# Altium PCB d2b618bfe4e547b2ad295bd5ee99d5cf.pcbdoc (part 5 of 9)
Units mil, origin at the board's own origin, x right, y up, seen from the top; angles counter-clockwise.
Board outline 5129 x 4161 mil, 8 copper layers (Top Layer, GND1, 内层2, VCC, 内层4, Inner5, GND2, Bottom Layer); 491 components, 452 nets, 2562 pads, 1124 vias.
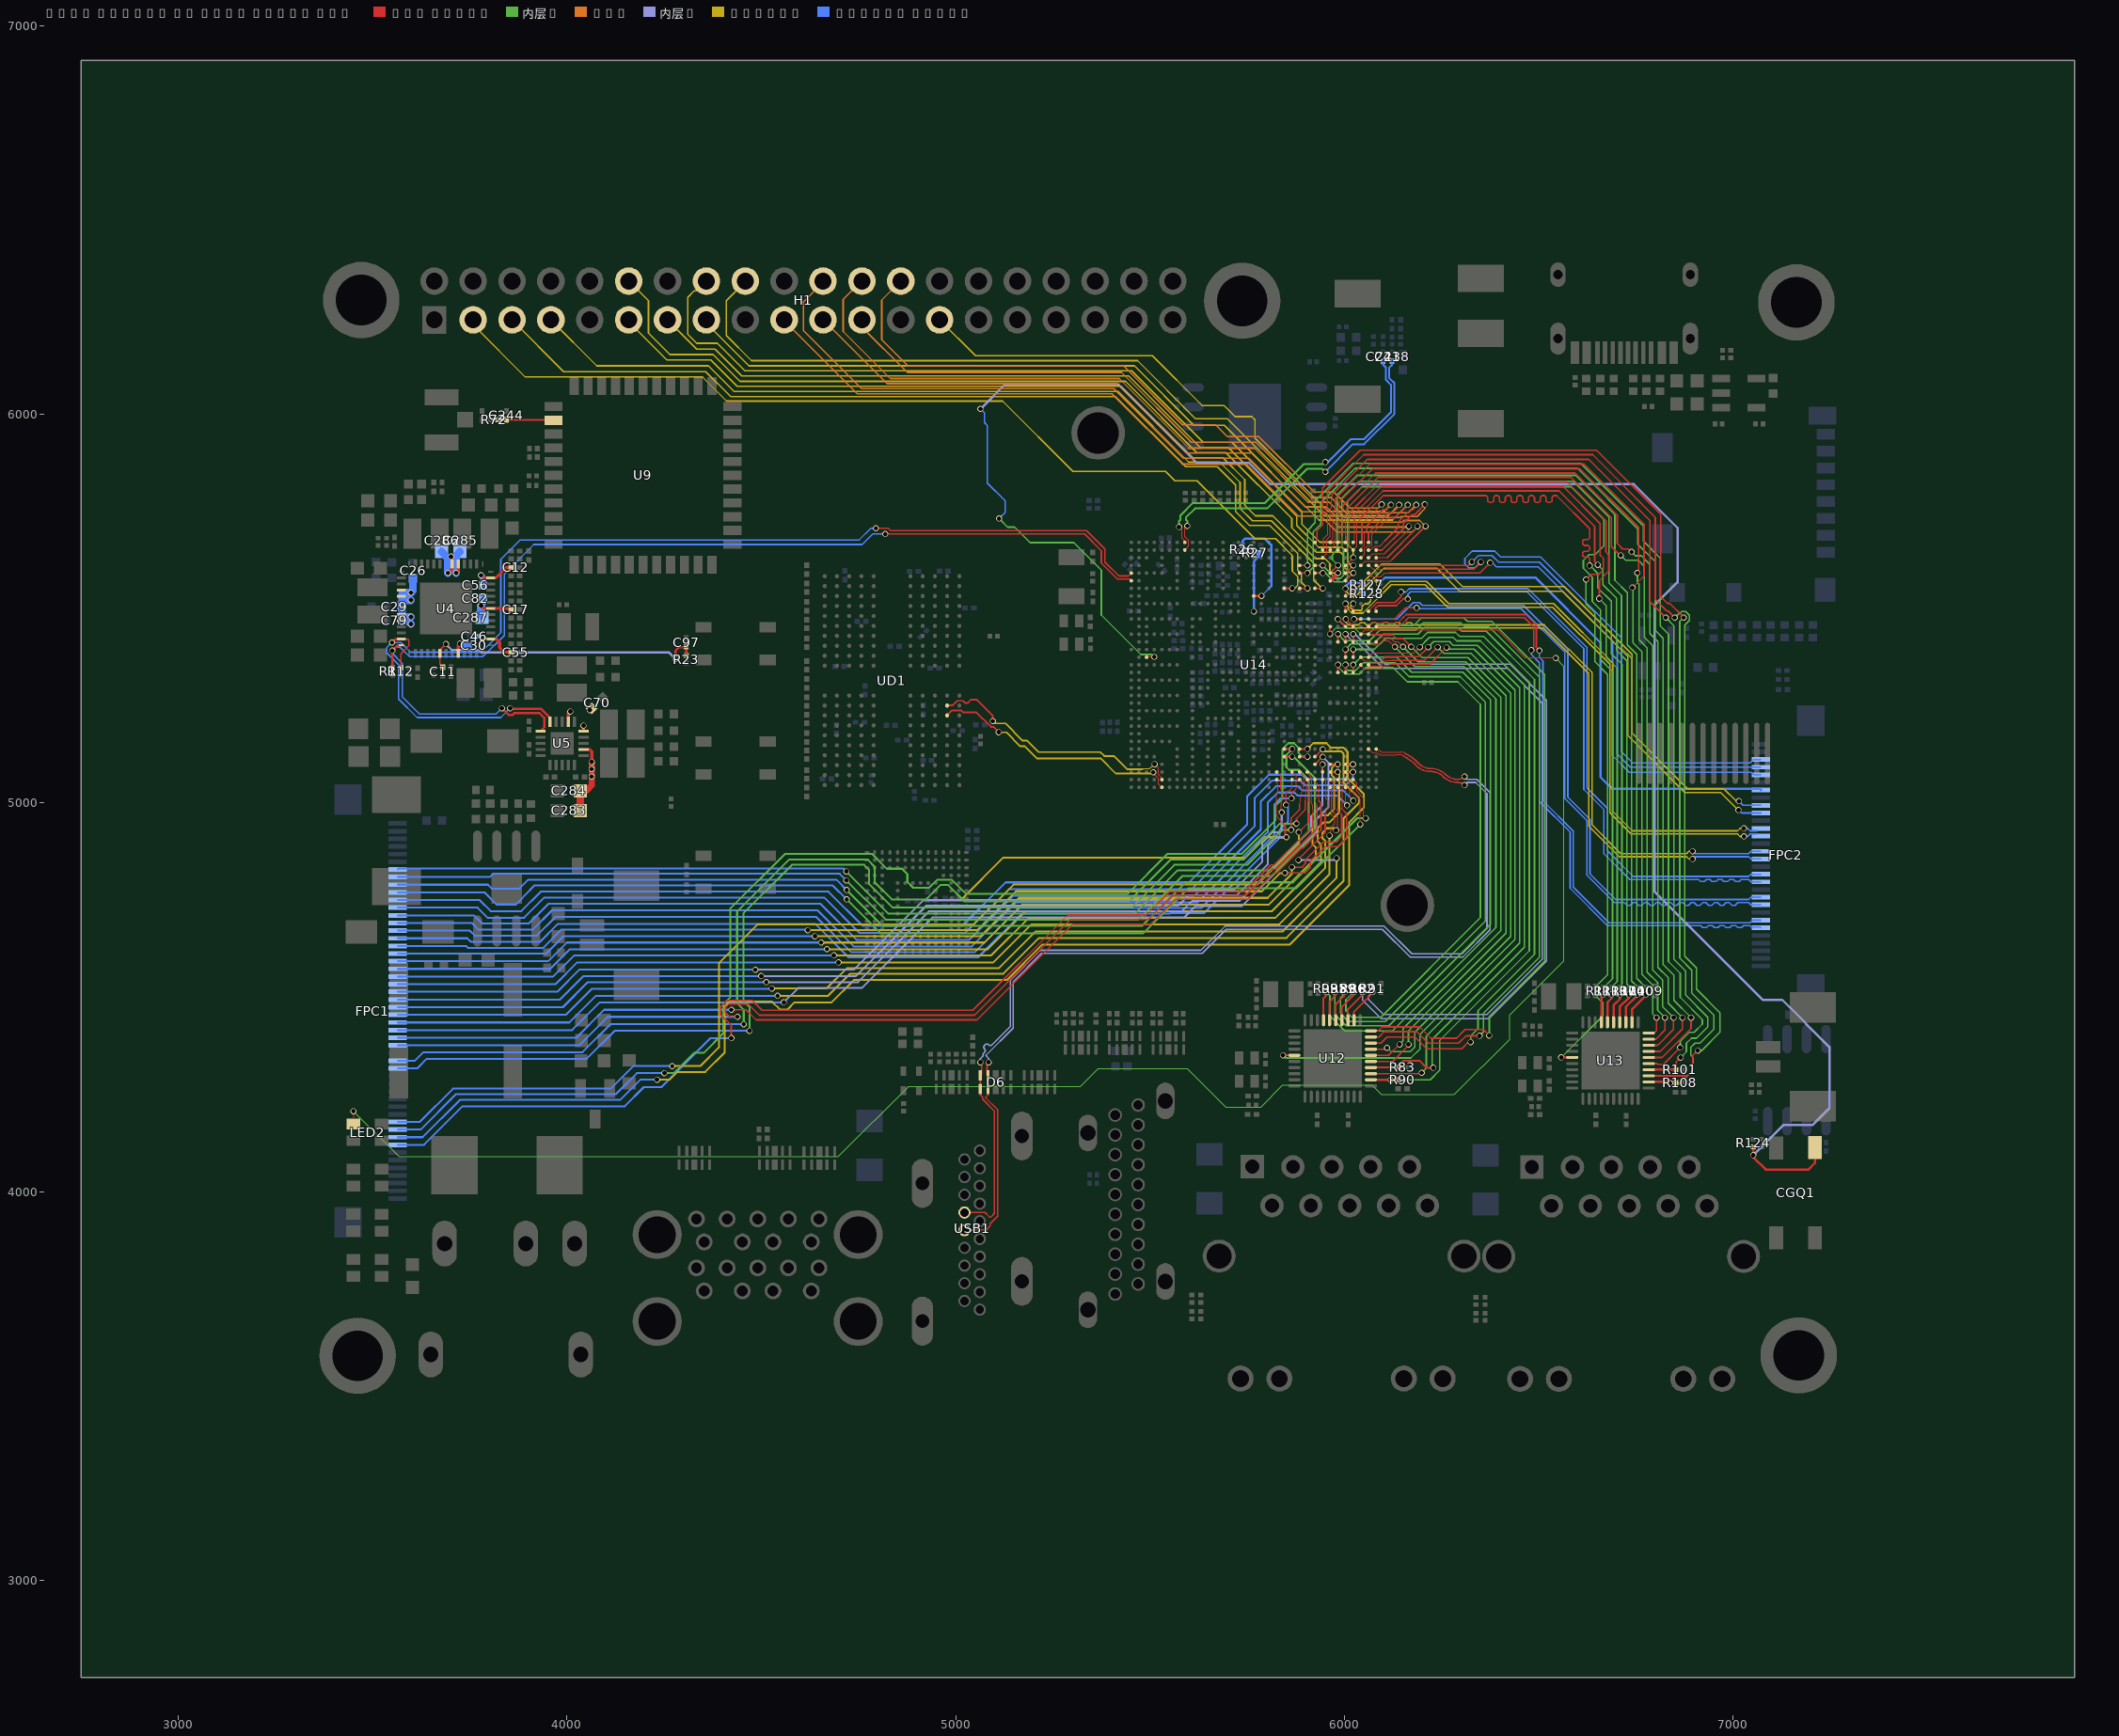
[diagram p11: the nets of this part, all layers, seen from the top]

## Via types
v1: diameter 15.75, hole 11.8, Top Layer to Bottom Layer, 497 vias
v2: diameter 15.7, hole 11.8, Top Layer to Bottom Layer, 335 vias
v3: diameter 15.75, hole 11.81, Top Layer to Bottom Layer, 279 vias
v4: diameter 24, hole 12, Top Layer to Bottom Layer, 13 vias

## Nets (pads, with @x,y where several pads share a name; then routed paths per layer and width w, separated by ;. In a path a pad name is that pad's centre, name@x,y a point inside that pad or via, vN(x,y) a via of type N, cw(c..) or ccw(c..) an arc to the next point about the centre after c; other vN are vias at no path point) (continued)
HTXCN: D6.5 D6.6 U14.B28 USB1.12 | length 2784.9
  Top Layer w3: U14.B28@6062.19,5138.91 6067.59,5133.51 ccw(c6078.21,5144.12) 6078.21,5129.11 6087.21,5129.11 6092.3,5124.02 6133.3,5124.02 cw(c6133.3,3512.36) 6141,5124 6145.7,5124.01 cw(c6145.7,5115.9) 6152,5121
  Top Layer w4: USB1.12@5022.89,3946.5 5075.5,3946.5 5087,3935 5091,3935 5100,3944 5100,4207.59 5069.46,4238.14 5069.46,4243.46 5063.63,4249.28 D6.6@5063.63,4264.67 D6.5@5063.63,4299.32 5067,4302.69 5067,4330 v1(5064,4333) ; 6152,5121 cw(c6096.03,5010.28) 6186.19,5095.5 ccw(c6219.89,5127.36) 6221,5081 cw(c6222.13,5033.84) 6255.36,5067.32 ccw(c6290.13,5102.35) 6290.13,5053 6292.13,5053 cw(c6292.13,5029.16) v1(6309,5046)
  内层4 w4: v1(5064,4333) 5064,4342.87 5070.49,4349.37 5070.49,4354.69 5074.36,4358.56 ccw(c5069.91,4363.01) 5074.36,4367.46 cw(c5078.81,4371.91) 5074.36,4376.36 5076.07,4378.07 cw(c5080.52,4373.61) 5084.97,4378.07 ccw(c5089.42,4382.52) 5093.87,4378.07 5141,4425.19 5141,4544.34 5217.68,4621.02 5631.02,4621.02 5693.02,4683.02 6102.98,4683.02 6174,4612 6302,4612 6367,4677 6367,5024 6338,5053 6316,5053 v1(6309,5046)
HTXCP: D6.4 D6.7 U14.A28 USB1.10 | length 2786.1
  Top Layer w3: U14.A28@6081.94,5138.93 6083.5,5137.3 ccw(c6086.37,5140.16) 6086.37,5136.11 6090.11,5136.11 6095.2,5131.02 6145.7,5131.01 cw(c6145.7,5112.46) 6155.61,5128.14
  Top Layer w4: USB1.10@5022.89,3900.97 5023.91,3902 5079,3902 5089,3912 5089,3918 5108.02,3937.02 5108.02,4210.91 5077.47,4241.46 5077.47,4243.46 5083.3,4249.28 D6.7@5083.3,4264.67 D6.4@5083.3,4299.33 5081,4301.63 5081,4329 v1(5085,4333) ; 6155.61,5128.14 cw(c6096.03,5010.28) 6192,5101 ccw(c6219.89,5127.36) 6220.81,5089 cw(c6222.13,5033.84) 6261,5073 ccw(c6290.13,5102.35) 6290.13,5061 6292.13,5061 ccw(c6292.13,5084.84) v1(6309,5068)
  内层4 w4: v1(5085,4333) 5085,4342.87 5078.51,4349.37 5078.51,4351.37 5148,4420.86 5148,4540 5221,4613 5634.34,4613 5696.34,4675 6098,4675 6169.02,4603.98 6305.32,4603.98 6375.02,4673.68 6375.02,5027.32 6341.34,5061 6316,5061 v1(6309,5068)
IR-RX: CGQ1.3 R124.1 U14.AL16 | length 5146.7
  Top Layer w3: U14.AL16@5491.39,5375.16 5510.16,5375.16 v2(5511,5376)
  Top Layer w6: R124.1@7052.62,4115.95 7052.62,4094.62 v2(7052,4094) 7052,4089 7084,4057 7194,4057 7210.88,4073.88 CGQ1.3@7210.88,4113.94
  内层2 w4: v2(5112,5732) 5134,5710 5152,5710 5192,5670 5304,5670 5375,5599 5375,5483.58 5476.58,5382 5505,5382 v2(5511,5376)
  内层4 w6: v2(5064,6014) 5127,6077 5419,6077 5621,5875 5755,5875 5810,5820 6745,5820 6857,5708 6857,5568 6798,5509 6798,4772 7076,4494 7126,4494 7248,4372 7248,4215 7205,4172 7130,4172 v2(7052,4094)
  Bottom Layer w4: v2(5064,6014) 5074,6004 5074,5979 5082,5971 5082,5823 5128,5777 5128,5748 v2(5112,5732)
LCD0-CLK: FPC1.43 U14.K31 | length 2944.3
  Top Layer w3: U14.K31@5904.64,5079.71 5914.45,5065.42 5915.07,5056.38 5914.99,5041.24 5914.45,5032.98 5915.07,5021.24 5914.22,5003.55 5917.93,4993.2 5918.93,4973.19
  Top Layer w4: v1(4423,4395) 4423,4428 4396,4455 4396,4476 4412,4492 4477,4492 4502,4467 5044,4467 5289,4712 5490,4712 5550,4772 5742,4772 5811,4841 5819,4841 5882,4904 5885,4904 5919,4938 5919,4973
  Bottom Layer w5: FPC1.43@3564.97,4120.52 3632.51,4120.52 3732,4220 4149,4220 4198,4269 4243,4269 4369,4395 v1(4423,4395)
LCD0-D0: FPC1.7 U14.N28 | length 2757.5
  Top Layer w5: U14.N28@5845.72,5138.93 v1(5865.72,5138.93)
  内层2 w5: v1(4719,4824) 4828,4715 5460,4715 5572,4827 5808,4827 5909,4928 5909,5060 5884,5085 5858,5085 5851,5092 5851,5124.22 v1(5865.72,5138.93)
  Bottom Layer w5: FPC1.7@3564.97,4829.18 3566.97,4831.18 4711.82,4831.18 v1(4719,4824)
LCD0-D1: FPC1.8 U14.N29 | length 2746.6
  Top Layer w5: U14.N29@5845.72,5119.25 v1(5865.72,5119.25)
  内层2 w5: v1(4719,4801) 4820,4700 5471,4700 5583,4812 5813,4812 5924,4923 5924,5065 5869.75,5119.25 v1(5865.72,5119.25)
  Bottom Layer w5: FPC1.8@3564.97,4809.48 3801.68,4809.48 3810.2,4818 4702,4818 v1(4719,4801)
LCD0-D2: FPC1.9 U14.D32 | length 2780.5
  Top Layer w3: U14.D32@6022.88,5060.51 6032.77,5050.61 6032.77,5030.23 6050,5013 6050,4966 v1(6055,4961)
  内层2 w5: v1(4720,4776) 4812,4684 5480,4684 5592,4796 5868,4796 6033,4961 v1(6055,4961)
  Bottom Layer w5: FPC1.9@3564.97,4789.81 3797.2,4789.81 3807,4780 3878,4780 3901,4803 4693,4803 v1(4720,4776)
LCD0-D3: FPC1.10 U14.D33 | length 2780
  Top Layer w3: U14.D33@6022.85,5040.79 6022.85,5026.85 6041,5008.7 v1(6041,4945)
  内层2 w5: v1(4720,4752) 4807,4665 5483,4665 5599,4781 5877,4781 v1(6041,4945)
  Bottom Layer w5: FPC1.10@3564.97,4770.11 3787.89,4770.11 3819,4739 3869,4739 3905,4775 3905,4776 3917,4788 4684,4788 v1(4720,4752)
LCD0-D4: FPC1.11 U14.E30 | length 2782.8
  Top Layer w5: U14.E30@6003.2,5099.56 v1(6022.2,5099.56)
  Bottom Layer w5: FPC1.11@3564.97,4750.44 3775.57,4750.44 3804,4722 3883,4722 3933,4772 4673,4772 4761,4684 5017,4684 5129,4796 5601,4796 5750,4945 5750,5017 5806,5073 5891,5073 5903,5061 5998.32,5061 6008,5070.68 6008,5093.57 6013.99,5099.56 v1(6022.2,5099.56)
LCD0-D5: FPC1.12 U14.E31 | length 2778.9
  Top Layer w5: U14.E31@6003.2,5079.88 v1(6022.2,5079.88)
  Bottom Layer w5: FPC1.12@3564.97,4730.74 3770.26,4730.74 3796,4705 3890,4705 3942,4757 4662,4757 4753,4666 5025,4666 5137,4778 5607,4778 5769,4940 5769,5012 5815,5058 5886,5058 5898,5046 6004,5046 6022.2,5064.2 v1(6022.2,5079.88)
LCD0-D6: FPC1.13 U14.E32 | length 2810.2
  Top Layer w3: U14.E32@6003.23,5060.51 6012.98,5050.75 6012.98,5016.02 v1(6023,5006)
  Bottom Layer w5: FPC1.13@3564.97,4711.06 3760.93,4711.06 3782,4690 3902,4690 3953,4741 4652,4741 4745,4648 5035,4648 5148,4761 5614,4761 5785,4932 5785,5004 5824,5043 5881,5043 5892,5032 5997,5032 v1(6023,5006)
LCD0-D7: FPC1.14 U14.E33 | length 2779.1
  Top Layer w3: U14.E33@6003.18,5040.81 6003.18,4997.82 v1(6007,4994)
  Bottom Layer w5: FPC1.14@3564.97,4691.38 3755.62,4691.38 3773,4674 3912,4674 3962,4724 4645,4724 4738,4631 5042,4631 5156,4745 5623,4745 5803,4925 5803,5001 5829,5027 5872,5027 5880,5019 5982,5019 v1(6007,4994)
LCD0-D8: FPC1.15 U14.M31 | length 2648.4
  Top Layer w3: U14.M31@5865.45,5080.07 5875.25,5070.27 5875.25,5035.39 5870.86,5031
  Top Layer w4: v1(5864,5012) 5864,5024.14 5870.86,5031
  Bottom Layer w5: FPC1.15@3564.97,4671.69 3750.3,4671.69 3763,4659 3923,4659 3971,4707 4641,4707 4732,4616 5049,4616 5163,4730 5632,4730 5820,4918 5820,4996 5836,5012 v1(5864,5012)
LCD0-D9: FPC1.16 U14.M32 | length 2621.5
  Top Layer w3: 5856,5030 5865.45,5039.45 U14.M32@5865.45,5060.37
  Top Layer w4: v1(5850,4995) 5850,5024 5856,5030
  Bottom Layer w5: FPC1.16@3564.97,4652.01 3743.99,4652.01 3753,4643 3931,4643 3977,4689 4639,4689 4725,4603 5058,4603 5170,4715 5551,4715 5553,4717 5640,4717 5834,4911 5834,4931 5855,4952 5855,4990 v1(5850,4995)
LCD0-D10: FPC1.17 U14.F32 | length 2730.5
  Top Layer w3: U14.F32@5983.53,5060.51 5993.34,5050.71 5993.34,4985.27
  Top Layer w4: v1(5847,4820) 5899,4820 5913,4834 5913,4850 5951,4888 5984,4888 6006,4910 6006,4972.6 5993.34,4985.27
  Inner5 w5: v1(4620,4673) 5055,4673 5155,4773 5788,4773 5835,4820 v1(5847,4820)
  Bottom Layer w5: FPC1.17@3564.97,4632.32 3740.68,4632.32 3746,4627 3938,4627 3985,4674 4619,4674 v1(4620,4673)
LCD0-D11: FPC1.18 U14.F33 | length 2699.4
  Top Layer w3: 5983.48,4985.23 U14.F33@5983.48,5040.81
  Top Layer w4: v1(5865,4835) 5891,4835 5900,4844 5900,4854 5946,4900 5979,4900 5993,4914 5993,4970.05 5983.48,4979.57 5983.48,4985.23
  Inner5 w5: v1(4638,4657) 5064,4657 5163,4756 5803,4756 5865,4818 v1(5865,4835)
  Bottom Layer w5: FPC1.18@3564.97,4612.64 3946.64,4612.64 3991,4657 v1(4638,4657)
LCD0-D12: FPC1.19 U14.G30 | length 2782.1
  Top Layer w5: U14.G30@5963.83,5099.56 v1(5982.83,5099.56)
  Inner5 w5: v1(4654,4641) 5074,4641 5171,4738 5805,4738 5927,4860 5927,4885 5918,4894 5918,4949 5937,4968 5957,4968 5974,4985 5974,5065 5968,5071 5968,5091 5976.56,5099.56 v1(5982.83,5099.56)
  Bottom Layer w5: FPC1.19@3564.97,4592.95 3951.95,4592.95 4000,4641 v1(4654,4641)
LCD0-D13: FPC1.20 U14.G31 | length 2777.1
  Top Layer w5: U14.G31@5963.83,5079.87 v1(5982.83,5079.87)
  Inner5 w5: v1(4669,4624) 5083,4624 5181,4722 5814,4722 5940,4848 5940,4893 5931,4902 5931,4935 5946,4950 5961,4950 5987,4976 5987,5075.71 v1(5982.83,5079.87)
  Bottom Layer w5: FPC1.20@3564.97,4573.27 3957.26,4573.27 4008,4624 v1(4669,4624)
LCD0-D14: FPC1.21 U14.G32 | length 2777.4
  Top Layer w3: U14.G32@5963.88,5060.51 5973.7,5050.69 5973.7,4973.3 5983,4964 5983,4934 v1(5979,4930)
  Inner5 w5: v1(4687,4608) 5092,4608 5189,4705 5823,4705 5951,4833 5951,4902 5944,4909 5944,4924 5955,4935 5974,4935 v1(5979,4930)
  Bottom Layer w5: FPC1.21@3564.97,4553.59 3964.59,4553.59 4019,4608 v1(4687,4608)
LCD0-D15: FPC1.22 U14.G33 | length 2745.5
  Top Layer w3: U14.G33@5963.82,5040.51 5966,5038.33 5966,4971 5975,4962 5975,4946 5965,4936 5965,4926 5962,4923 5962,4921 v1@5963.88,4922.88
  Inner5 w5: v1(4699,4590) 5097,4590 5195,4688 5833,4688 5962,4817 v1(5962,4916)
  Bottom Layer w5: FPC1.22@3564.97,4533.9 3970.89,4533.9 4027,4590 v1(4699,4590)
LCD0-D16: FPC1.23 U14.P31 | length 2635
  Top Layer w3: U14.P31@5826.15,5080.07 5835.95,5070.27 5835.95,5036.61 5836.36,5036.2 5839.08,5025.26 5839.15,5007.57 5836.45,4999.92 5836.99,4988.57 v1(5839,4976)
  Top Layer w4: v1@5836,4979 v1(5839,4976)
  内层4 w5: v1(4485,4571) 4738,4571 4917,4750 5568,4750 5595,4777 5717,4777 5789,4849 5789,4898 5816,4925 5835,4925 5839,4929 v1(5839,4976)
  Bottom Layer w5: FPC1.23@3564.97,4514.22 3975.22,4514.22 4032,4571 v1(4485,4571)
LCD0-D17: FPC1.24 U14.P32 | length 3543
  Top Layer w3: U14.P32@5826.14,5058.6 5828.27,5050.09 5829.02,5046.25 5829.37,5036.98 5829.13,5028.15 5829.13,5028.04 5826,5024.91 5826,4969.64 5828.24,4963.11 5833.8,4956.24 ; 5833.78,4956.22 5846,4944
  Top Layer w4: 5846,4944 5848,4942 5848,4915 v1(5851,4912)
  内层4 w5: v1(4500,4555) 4744,4555 4925,4736 5573,4736 5600,4763 5724,4763 5803,4842 5803,4888 5827,4912 v1(5851,4912)
  Inner5 w5: 5017,4754 5122,4859 5743,4859 5796,4912 v1(5851,4912)
  Bottom Layer w5: FPC1.24@3564.97,4494.52 3982.53,4494.52 4043,4555 v1(4500,4555)
LCD0-D18: FPC1.25 U14.H31 | length 2737
  Top Layer w4: v1(5944,5099) 5944.15,5098.85 U14.H31@5944.15,5079.88
  内层4 w5: v1(4513,4539) 4749,4539 4931,4721 5581,4721 5608,4748 5730,4748 5915,4933 5915,4966 5944,4995 v1(5944,5099)
  Bottom Layer w5: FPC1.25@3564.97,4474.85 3989.84,4474.85 4054,4539 v1(4513,4539)
LCD0-D19: FPC1.26 U14.H32 | length 2961.3
  Top Layer w3: U14.H32@5944.18,5060.51 5945.1,5061.43 5950,5061.43 5953,5058.43 5953,5010.7 5958.74,5004.96 5958.74,4985.74 5951,4978 5951,4971
  Top Layer w4: v1(5882,4853) 5882,4855 5951,4924 5951,4971
  内层4 w5: v1(5882,4853) 5975,4853 v1(5980,4858)
  Inner5 w5: v1(4527,4523) 4668,4523 4720,4575 5111,4575 5206,4670 5842,4670 5980,4808 v1(5980,4858)
  Bottom Layer w5: FPC1.26@3564.97,4455.15 3997.16,4455.15 4064,4522 4526,4522 v1(4527,4523)
LCD0-D20: FPC1.27 U14.J29 | length 3030.2
  Top Layer w4: U14.J29@5924.46,5119.25 5943.46,5138.25 v1(5944.46,5138.25)
  Inner5 w5: v1(4542,4504) 4672,4504 4729,4561 5123,4561 5215,4653 5851,4653 5998,4800 5998,4960 6038,5000 6038,5012 5998,5052 5998,5127 5992,5133 5949.71,5133 v1(5944.46,5138.25)
  Bottom Layer w5: FPC1.27@3564.97,4435.48 4006.47,4435.48 4075,4504 v1(4542,4504)
LCD0-D21: FPC1.28 U14.J30 | length 2813.7
  Top Layer w4: U14.J30@5924.46,5099.56 5943.46,5118.56 v1(5944.46,5118.56)
  内层4 w5: v1(4558,4487) 4595,4524 4759,4524 4941,4706 5589,4706 5618,4735 5737,4735 5928,4926 5928,4958 5959,4989 5959,5104.02 v1(5944.46,5118.56)
  Bottom Layer w5: FPC1.28@3564.97,4415.78 4013.78,4415.78 4085,4487 v1(4558,4487)
LCD0-D22: FPC1.29 U14.J32 | length 2754.7
  Top Layer w3: U14.J32@5924.48,5060.51 5924.48,5054.71 5934.27,5044.91 5934.27,5005.56
  Top Layer w4: v1(4423,4468) 4461,4468 4487,4442 5055,4442 5301,4688 5502,4688 5566,4752 5751,4752 5819,4820 5826,4820 5890,4884 5894,4884 5940.04,4930.04 5940.04,4999.8 5934.27,5005.56
  Bottom Layer w5: FPC1.29@3564.97,4396.1 4024.11,4396.1 4096,4468 v1(4423,4468)
LCD0-D23: FPC1.30 U14.J33 | length 2797.3
  Top Layer w3: U14.J33@5924.31,5040.15 5926.01,5034.28 5926.16,5014.28 5925.23,5003.47 5929.75,4994.05
  Top Layer w4: v1(4439,4450) 4419,4450 4408,4461 4408,4474 4417,4483 4466,4483 4495,4454 5049,4454 5295,4700 5496,4700 5558,4762 5746,4762 5814,4830 5823,4830 5887,4894 5890,4894 5929.75,4933.75 5929.75,4994.05 5929.75,4994.35
  Bottom Layer w5: FPC1.30@3564.97,4376.41 4031.41,4376.41 4105,4450 v1(4439,4450)
LCD0-DE: FPC1.40 U14.K32 | length 2919.7
  Top Layer w3: 5906.88,4974.2 5906.88,4997.45 5908.54,5020.82 5908.56,5021.22 5907.94,5033.02 5908.5,5041.47 5908.53,5048.86 5904.77,5060.51 U14.K32@5907.18,5058.11
  Top Layer w4: v1(5883,4925) 5907.18,4949.18 5907.18,4974
  Inner5 w5: v1(4271,4323) 4343,4323 4391,4371 4391,4588 4491,4688 5047,4688 5149,4790 5776,4790 5883,4897 v1(5883,4925)
  Bottom Layer w5: FPC1.40@3564.97,4179.56 3621.57,4179.56 3707,4265 4113,4265 4171,4323 v1(4271,4323)
LCD0-HSYNC: FPC1.42 U14.L28 | length 3317
  Top Layer w5: U14.L28@5885.09,5138.93 v1(5905.09,5138.93)
  Inner5 w5: v1(4232,4288) 4264,4288 4284,4308 4356,4308 4406,4358 4406,4477 4418,4489 4528,4489 4548,4469 4568,4469 4586,4487 4681,4487 4739,4545 5132,4545 5223,4636 5860,4636 6012,4788 6012,4950 6050,4988 6050,5023 6008.32,5064.68 6008.32,5131.68 5997,5143 5965,5143 5954,5154 5920.16,5154 v1(5905.09,5138.93)
  Bottom Layer w5: FPC1.42@3564.97,4140.19 3629.2,4140.19 3725,4236 4137,4236 4189,4288 v1(4232,4288)
LCD0-PWM: FPC1.32 U14.L31 | length 3050.8
  Top Layer w3: U14.L31@5885.15,5080.07 5894.98,5070.24 5895.03,5059.01 5896.04,5055.11 5898.18,5052.43 5901.72,5040.93 5898.86,5017.8 5899,5005.68 5899.01,5005.17
  Top Layer w4: v1(5877,4947) 5877,4960 5899,4982 5899,5005.68 5899,5006
  内层2 w5: v1(4455,4431) 4455,4468 4438,4485 4438,4721 4572,4855 4773,4855 4792,4836 4792,4796 4836,4752 4924,4752 4961,4789 4981,4789 5023,4747 5446,4747 5554,4855 5742,4855 5834,4947 v1(5877,4947)
  Bottom Layer w5: FPC1.32@3564.97,4337.05 3609.05,4337.05 3631,4359 4040,4359 4112,4431 v1(4455,4431)
LCD0-RST: FPC1.33 U14.L32 | length 3006.3
  Top Layer w3: U14.L32@5884.76,5058.85 5892.33,5049.35 5894.8,5041.31 5893.95,5034.44 5891.48,5029.57 5887.54,5020.69 5884.84,4996.2
  Top Layer w4: v1(5863,4931) 5863,4961 5884.8,4982.8 5884.8,4996.42
  内层2 w5: v1(4470,4414) 4470,4476 4454,4492 4454,4716 4579,4841 4765,4841 4777,4829 4777,4792 4838,4731 5453,4731 5563,4841 5750,4841 5840,4931 v1(5863,4931)
  Bottom Layer w5: FPC1.33@3564.97,4317.36 3615.36,4317.36 3640,4342 4051,4342 4123,4414 v1(4470,4414)
LCD0-VSYNC: FPC1.41 U14.L29 | length 3182.7
  Top Layer w5: U14.L29@5885.09,5119.25 v1(5905.09,5119.25)
  内层2 w5: v1(4251,4305) 4275,4305 4327,4357 4352,4357 4402,4407 4402,4482 4420,4500 4420,4728 4561,4869 4785,4869 4823,4831 4862,4831 4876,4817 4876,4797 4891,4782 4932,4782 4953,4803 4990,4803 5027,4766 5442,4766 5545,4869 5736,4869 5823,4956 5823,4993 5841,5011 5841,5139 5856,5154 5870.33,5154 5882,5142.33 5882,5129 5891.75,5119.25 v1(5905.09,5119.25)
  Bottom Layer w5: FPC1.41@3564.97,4159.89 3623.89,4159.89 3715,4251 4126,4251 4180,4305 v1(4251,4305)
LEDC: LED2.3 U14.C13 | length 4864.7
  Top Layer w3: v2(3451,4207) 3451.16,4206.84 LED2.3@3451.16,4174.43 ; U14.C13@6042.57,5434.21 6052.36,5444 6395,5444 6466,5373 v2(6544,5373)
  内层2 w3: v2(3451,4207) 3569,4089 4697,4089 4878,4270 5320,4270 5366,4316 5597,4316 5696,4217 5784,4217 5840,4273 6072,4273 6096,4249 6282,4249 6424,4391 6424,4453 6564,4593 6564,5353 v2(6544,5373)
MCSI0-CKN: FPC2.12 U14.A10 | length 1629.1
  Top Layer w4: U14.A10@6081.94,5493.27 6079.93,5495.28 6079.93,5500.93 6087,5508 6134.16,5508 6151.16,5525 v2(6163,5525)
  Bottom Layer w4: v2(6163,5525) 6163,5536 6170.34,5543.34 6469.66,5543.34 6616,5397 6616,5035 6668,4983 6668,4869 6734.06,4802.94 6911.21,4802.94 6916.21,4797.94 6926.21,4797.94 6931.21,4802.94 6941.21,4802.94 6946.21,4797.94 6956.21,4797.94 6961.21,4802.94 6971.21,4802.94 6976.21,4797.94 6986.21,4797.94 6991.21,4802.94 7001.21,4802.94 7006.21,4797.94 7016.21,4797.94 7021.21,4802.94 7040.56,4802.94 7046.4,4797.1 FPC2.12@7072.02,4797.1
MCSI0-CKP: FPC2.13 U14.B10 | length 1625.8
  Top Layer w4: U14.B10@6062.26,5493.26 6062.26,5494.33 6083.93,5516 6130.84,5516 6146,5531.16 v2(6146,5543)
  Bottom Layer w4: v2(6146,5543) 6158.69,5543 6167.03,5551.34 6472.66,5551.34 6624,5400 6624,5039 6677,4986 6677,4877 6743.06,4810.94 7040.56,4810.94 7046.4,4816.78 FPC2.13@7072.02,4816.78
MCSI0-D0N: FPC2.6 U14.A12 | length 1690.5
  Top Layer w3: U14.A12@6081.94,5453.9 6141.9,5453.9 6158,5470
  Top Layer w4: 6158,5470 6165,5477 6463,5477 6487,5453 6487,5399 v2(6481,5393)
  Bottom Layer w4: v2(6481,5393) 6481,5382 6502,5361 6502,5004 6581,4925 6581,4780.69 6676.69,4685 6916.73,4685 6921.73,4680 6931.73,4680 6936.73,4685 6946.73,4685 6951.73,4680 6961.73,4680 6966.73,4685 6976.73,4685 6981.73,4680 6991.73,4680 6996.73,4685 7006.73,4685 7011.73,4680 7021.73,4680 7026.73,4685 7043,4685 7047,4681 7070.02,4681 FPC2.6@7072.02,4678.99
MCSI0-D0P: FPC2.7 U14.B12 | length 1692.6
  Top Layer w3: U14.B12@6062.26,5453.91 6072.36,5464 6138,5464 6150,5476
  Top Layer w4: 6150,5476 6159,5485 6466.31,5485 6494,5457.31 6494,5400 v2(6502,5392)
  Bottom Layer w4: v2(6502,5392) 6502,5375 6511,5366 6511,5006 6589,4928 6589,4784 6681,4692 7044,4692 7050.68,4698.68 FPC2.7@7072.02,4698.68
MCSI0-D1N: FPC2.9 U14.B11 | length 1700.5
  Top Layer w3: U14.B11@6062.26,5473.58 6128.58,5473.58 6137,5482
  Top Layer w4: 6137,5482 6157,5502 v2(6186,5502)
  Bottom Layer w4: v2(6186,5502) 6187.68,5500.32 6454.68,5500.32 6567.05,5387.95 6567.05,5011.95 6624,4955 6624,4814.53 6694.64,4743.89 6720.08,4743.89 6727.33,4736.65 6735.08,4736.65 6742.33,4743.89 6750.08,4743.89 6757.33,4736.65 6765.08,4736.65 6772.33,4743.89 6780.08,4743.89 6787.33,4736.65 6795.08,4736.65 6802.33,4743.89 6810.08,4743.89 6817.33,4736.65 6825.08,4736.65 6832.33,4743.89 6840.08,4743.89 6847.33,4736.65 6855.08,4736.65 6862.33,4743.89 6870.08,4743.89 6877.33,4736.65 6885.08,4736.65 6892.33,4743.89 6900.08,4743.89 6907.33,4736.65 6915.08,4736.65 6922.33,4743.89 6930.08,4743.89 6937.33,4736.65 6945.08,4736.65 6952.33,4743.89 6960.08,4743.89 6967.33,4736.65 6975.08,4736.65 6982.33,4743.89 6990.08,4743.89 6997.33,4736.65 7005.08,4736.65 7012.33,4743.89 7040.56,4743.89 7046.4,4738.05 FPC2.9@7072.02,4738.05
MCSI0-D1P: FPC2.10 U14.C11 | length 1705.2
  Top Layer w5: v2(6025,5473) 6042,5473 U14.C11@6042.58,5473.58
  Bottom Layer w4: v2(6025,5473) 6135,5473 6177.35,5515.35 6193.65,5515.35 6200.68,5508.32 6460.68,5508.32 6575.05,5393.95 6575.05,5014.95 6632,4958 6632,4817.84 6697.95,4751.89 7040.56,4751.89 7046.4,4757.73 FPC2.10@7072.02,4757.73
MCSI0-D2N: FPC2.15 U14.E12 | length 1606.8
  Top Layer w4: v1(5983.2,5472.9) 5984.2,5472.9 U14.E12@6003.2,5453.9
  Inner5 w4: v1(5983.2,5472.9) 6005.75,5450.34 6511.34,5450.34 6629,5332.69 6629,4940.69 6707.69,4862 6880.15,4862 6886.15,4856 v2(6896,4856)
  Bottom Layer w4: v2(6896,4856) 6902,4862 7040.56,4862 7046.4,4856.15 FPC2.15@7072.02,4856.15
MCSI0-D2P: FPC2.16 U14.D12 | length 1607.1
  Top Layer w4: v1(6004,5473) 6022.9,5454.1 U14.D12@6022.9,5453.9
  Inner5 w4: v1(6004,5473) 6004,5465 6010.66,5458.34 6036.66,5458.34 6041.66,5463.34 6051.66,5463.34 6056.66,5458.34 6066.66,5458.34 6071.66,5463.34 6081.66,5463.34 6086.66,5458.34 6096.66,5458.34 6101.66,5463.34 6111.66,5463.34 6116.66,5458.34 6126.66,5458.34 6131.66,5463.34 6141.66,5463.34 6146.66,5458.34 6156.66,5458.34 6161.66,5463.34 6171.66,5463.34 6176.66,5458.34 6514.66,5458.34 6637,5336 6637,4944 6711,4870 6880.15,4870 6886.15,4876 v2(6896,4876)
  Bottom Layer w4: v2(6896,4876) 6902,4870 7040.56,4870 7046.4,4875.85 FPC2.16@7072.02,4875.85
MCSI0-D3N: FPC2.18 U14.E10 | length 1619.2
  Top Layer w4: v1(6003,5513) 6003,5493.47 U14.E10@6003.2,5493.27
  Inner5 w4: v1(6003,5513) 6010,5506 6010,5498.1 6019.44,5488.66 6047.66,5488.66 6121,5562 6208,5562 6266,5504 6536,5504 6683,5357 6683,4974.69 6737.38,4920.3 7011.55,4920.3 7017.86,4914 v2(7028,4914)
  Bottom Layer w4: v2(7028,4914) 7037.85,4914 7044.15,4920.3 FPC2.18@7062.34,4920.3
MCSI0-D3P: FPC2.19 U14.D10 | length 1616.6
  Top Layer w4: U14.D10@6022.9,5493.27 6022.9,5512.9 v1(6023,5513)
  Inner5 w4: v1(6023,5513) 6017,5507 6017,5501 6022.34,5495.66 6043.34,5495.66 6046.01,5498.33 6046.01,5506.01 6052.78,5512.78 6060.46,5512.78 6067.23,5519.54 6067.23,5527.23 6073.99,5533.99 6081.68,5533.99 6117.69,5570 6211.31,5570 6268.31,5513 6538.31,5513 6691,5360.31 6691,4978 6740.7,4928.3 7011.55,4928.3 7017.86,4934.61 v2(7027.71,4934.61)
  Bottom Layer w4: v2(7027.71,4934.61) 7037.85,4934.61 7044.15,4928.3 7062.34,4928.3
MCSI0-MCLK: FPC2.24 U14.A6 | length 1429.7
  Top Layer w6: U14.A6@6081.94,5572.01 6081.94,5571.06 v2(6089,5564)
  Bottom Layer w6: v2(6089,5564) 6105,5580 6492,5580 6659,5413 6659,5067 6689.89,5036.11 7069.24,5036.11 FPC2.24@7072.02,5033.32
MCSI0-PWDN: FPC2.28 U14.B4 | length 1534
  Top Layer w3: U14.B4@6064.06,5610.26 6074.92,5601.77 6084.19,5601.46 6089.96,5601.82 6105.25,5601.87
  Top Layer w4: 6104.98,5602 6333,5602 v2(6351,5620)
  Bottom Layer w4: v2(6351,5620) 6336,5605 6320,5605 6310,5615 6310,5629 6329,5648 6387,5648 6402,5633 6505,5633 6713,5425 6713,5132 6742,5103 7044,5103 7053.06,5112.06 FPC2.28@7072.02,5112.06
MCSI0-RSTN: FPC2.27 U14.A4 | length 1398.5
  Top Layer w4: U14.A4@6081.94,5611.39 6319.39,5611.39 v2(6328,5620)
  Bottom Layer w4: v2(6328,5620) 6345,5637 6380,5637 6397,5620 6502,5620 6702,5420 6702,5126 6735.62,5092.38 FPC2.27@7072.02,5092.38
MCSI0-SCK: FPC2.21 R127.2 U14.E8 | length 1561.8
  Top Layer w4: U14.E8@6003.2,5532.64 v1(6003.2,5551.64)
  Inner5 w4: v1(6003.2,5551.64) 6003.2,5545.8 6013,5536 6034,5536 6102,5604 6238,5604 6297,5545 6561,5545 6729,5377 6729,5174 6876,5027 6968,5027 7013,4982 v2(7014,4982)
  Bottom Layer w4: v2(7014,4982) 7021.73,4974.27 FPC2.21@7072.02,4974.27
  Bottom Layer w6: v1(6003.2,5551.64) 6003.2,5557.2 6012,5566 6044.49,5566 R127.2@6048.49,5562
MCSI0-SDA: FPC2.22 R128.2 U14.D8 | length 1501.4
  Top Layer w4: U14.D8@6022.89,5532.64 v1(6022.89,5551.64)
  Inner5 w4: v1(6022.89,5551.64) 6032.64,5551.64 6096,5615 6246,5615 6304,5557 6566,5557 6740,5383 6740,5180 6883,5037 6976,5037 7008,5005 v2(7015,5005)
  Bottom Layer w4: v2(7015,5005) 7026.05,4993.95 FPC2.22@7072.02,4993.95
  Bottom Layer w6: v1(6022.89,5551.64) 6032.36,5551.64 6045,5539 R128.2@6048.49,5539
MCSI0-USER: FPC2.26 U14.B5 | length 1427.4
  Top Layer w3: U14.B5@6062.26,5591.69 6071.95,5582 6094,5582 6104,5592 6115.91,5592
  Top Layer w4: 6115.91,5592 6349,5592 v2(6375,5618)
  Bottom Layer w4: v2(6375,5618) 6381,5618 6391,5608 6499,5608 6690,5417 6690,5122 6733,5079 7047,5079 7053.31,5072.69 FPC2.26@7072.02,5072.69
MICIN3N: C241.1 U14.AF1 | length 869.5
  Top Layer w3: v1(5575,5710) 5576.32,5710 5582.69,5703.63 5582.69,5681.54 5589.69,5674.54 U14.AF1@5589.69,5670.41
  内层2 w5: v1(5575,5710) 5575,5725.71 5578.5,5729.21 5578.5,5740.01 5610.49,5772 5796,5772 5896,5872 5946,5872 v2(5951,5877)
  Bottom Layer w5: v2(5951,5877) 5958,5877 6017,5936 6051,5936 6120,6005 6120,6076.27 6106.76,6089.51 6106.76,6120.23 6099.76,6127.23 C241.1@6099.76,6136.99
MICIN3P: C238.1 U14.AF2 | length 893.7
  Top Layer w3: U14.AF2@5589.69,5650.71 5599.49,5660.51 5599.49,5675.79 5589.69,5685.59 5589.69,5706.53 v1(5596,5712.84) v1@5596,5713
  内层2 w5: v1(5596,5712.84) 5596,5725.71 5592.5,5729.21 5592.5,5734.21 5616.29,5758 5801.8,5758 5903.8,5860 5943,5860 v2(5951,5852)
  Bottom Layer w5: v2(5951,5852) 6022,5923 6050.73,5923 6129,6001.27 6129,6080 6115.76,6093.24 6115.76,6120.23 6122.76,6127.23 C238.1@6122.76,6136.99
PE0: H1.12 U14.E6 | length 2282.3
  Top Layer w4: U14.E6@6003.2,5572.01 6023,5591.8 v1(6023,5592)
  Inner5 w4: H1.12@4159,6343 4210,6292 4210,6209 4265,6154 4376,6154 4445,6085 5437,6085 5620,5902 5695,5902 5865,5732 5865,5708 5928,5645 5990,5645 5997.37,5637.63 5997.37,5609.63 6015,5592 v1(6023,5592)
PE1: H1.21 U14.C4 | length 1981.7
  Top Layer w3: U14.C4@6042.32,5611.32 6052.23,5621.23 6117.21,5621.21 6123,5627
  Top Layer w4: 6123,5627 6208,5712 v1(6209,5712)
  VCC w4: H1.21@4659,6243 4660,6243 4824,6079 5415,6079 5594,5900 5761,5900 5899,5762 5954,5762 5993,5723 6148,5723 6152,5727 6194,5727 v1(6209,5712)
PE2: H1.13 U14.E5 | length 2082
  Top Layer w4: U14.E5@6003.2,5591.69 v1(6023.2,5611.69)
  Inner5 w4: H1.13@4259,6243 4334,6168 4381,6168 4450,6099 5445,6099 5629,5915 5701,5915 5878,5738 5878,5714 5934,5658 5995,5658 6009,5644 6009,5620.24 6016.6,5612.64 6022.26,5612.64 v1(6023.2,5611.69)
PE3: H1.16 U14.E4 | length 2168.4
  Top Layer w4: U14.E4@6003.2,5611.38 v1(6023.2,5631.38)
  Inner5 w4: H1.16@4359,6343 4333.57,6317.57 4327.57,6317.57 4311,6301 4311,6206 4334,6183 4387,6183 4458,6112 5453,6112 5637,5928 5711,5928 5891,5748 5891,5717 5937,5671 6003,5671 6023.2,5650.8 v1(6023.2,5631.38)
PE4: H1.15 U14.C3 | length 2240.7
  Top Layer w3: U14.C3@6042.49,5631.01 6052.31,5640.83 6052.31,5654.77 6058.1,5660.55 6067.72,5660.55 6071.75,5664.58 6071.75,5692.56 6113.19,5734 6121,5734
  Top Layer w4: 6121,5734 6131,5734 6163,5766 v1(6163,5767)
  Inner5 w4: H1.15@4359,6243 4359,6234 4468,6125 5460,6125 5613,5972 5691,5972 5935,5728 6124,5728 v1(6163,5767)
PE5: H1.22 U14.B3 | length 2057.8
  Top Layer w3: U14.B3@6062.19,5631.01 6072.08,5640.9 6102.9,5640.9 6107,5645
  Top Layer w4: 6107,5645 6166,5704 v1(6166,5712)
  VCC w4: H1.22@4659,6343 4659,6340 4609,6290 4609,6215 4758,6066 5407,6066 5586,5887 5754,5887 5892,5749 5947,5749 5986,5710 6164,5710 v1(6166,5712)
PE6: H1.19 U14.A3 | length 2005.1
  Top Layer w3: U14.A3@6081.89,5631.01 6109.95,5630.95
  Top Layer w4: 6109.95,5630.95 6188,5709 v1(6188,5712)
  VCC w4: H1.19@4559,6243 4559,6241 4747,6053 5402,6053 5583,5872 5748,5872 5882,5738 5940,5738 5980.88,5697.12 6175.12,5697.12 6188,5710 v1(6188,5712)
PE7: H1.24 U14.A2 | length 2046.4
  Top Layer w4: U14.A2@6081.94,5650.74 6096.74,5650.74 6152,5706 6152,5720 6174,5742 6181,5742 v1(6207,5768)
  VCC w4: H1.24@4759,6343 4758,6343 4711,6296 4711,6213 4832,6092 5421,6092 5600,5913 5768,5913 5907,5774 5961,5774 6000,5735 6144,5735 6146,5737 6187,5737 6207,5757 v1(6207,5768)
PE8: H1.23 U14.B2 | length 1831.6
  Top Layer w3: U14.B2@6062.19,5650.71 6067.4,5650.71 6076.93,5660.24 6090.24,5660.24 6104,5674
  Top Layer w4: 6104,5674 6139,5709 6139,5723 6170,5754 6175.66,5754 6185,5763.34 v1(6185,5767)
  VCC w4: H1.23@4759,6243 4759,6225 4876,6108 5427,6108 5607,5928 5773,5928 5915,5786 5966,5786 6005,5747 6165,5747 v1(6185,5767)
PE9: H1.18 U14.B1 | length 2230.2
  Top Layer w4: U14.B1@6062.19,5670.41 6062.13,5695.03 6112.1,5745 6122,5745 6141,5764 v1(6141,5767)
  Inner5 w4: H1.18@4459,6343 4459,6341 4410,6292 4410,6203 4475,6138 5468,6138 5617,5989 5699,5989 5949,5739 6113,5739 v1(6141,5767)
PE10: H1.27 U14.C2 | length 1552.7
  Top Layer w3: U14.C2@6042.49,5650.71 6042.49,5655.23 6052.3,5665.06 6052.3,5696.11 6057.9,5701.71
  Top Layer w4.5: 6057.9,5701.71 6057.9,5712.71 6100.19,5755 6106.55,5755 6118.55,5767 v1(6120,5767)
  Inner5 w4: H1.27@4959,6243 5051,6151 5506,6151 5634,6023 5690,6023 5719,5994 5762,5994 5770,5986 5770,5939 5959,5750 6103,5750 v1(6120,5767)
PE11: H1.7 U14.J7 | length 2356
  Top Layer w4: U14.J7@5924.46,5552.32 v1(5944.46,5552.32)
  Inner5 w4: H1.7@3959,6243 4077,6125 4364,6125 4430,6059 5418,6059 5600,5877 5680,5877 5732,5825 5732,5758 5764,5726 5812,5726 5921,5617 5921,5574 5942.68,5552.32 v1(5944.46,5552.32)
PE12: H1.26 U14.C1 | length 1760.1
  Top Layer w4: U14.C1@6042.57,5670.43 6045,5672.86 6045,5717 v1(6096,5768)
  VCC w4: H1.26@4859,6343 4810,6294 4810,6192 4878,6124 5433,6124 5584,5973 5669,5973 5699,5943 5780,5943 5923,5800 5973,5800 6014,5759 6087,5759 v1(6096,5768)
PE13: H1.11 U14.G6 | length 2174.9
  Top Layer w10: U14.G6@5963.83,5572.01 v1(5983.83,5592.01)
  Inner5 w4: H1.11@4159,6243 4159,6238 4257,6140 4370,6140 4438,6072 5426,6072 5610,5888 5688,5888 5744,5832 5744,5766 5771,5739 5816,5739 5926,5629 5950,5629 5963,5616 5963,5598 5969,5592 v1(5983.83,5592.01)
PE14: H1.5 U14.L7 | length 2429.8
  Top Layer w4: U14.L7@5885.09,5552.32 v1(5905.09,5552.32)
  Inner5 w4: H1.5@3859,6243 3992,6110 4357,6110 4421,6046 5411.41,6046 5592.41,5865 5673,5865 5720,5818 5720,5750 5756,5714 5808,5714 5880,5642 5880,5599 5890,5589 5890,5567.41 v1(5905.09,5552.32)
PE15: H1.3 U14.N7 | length 2485.9
  Top Layer w4: U14.N7@5845.72,5552.32 v1(5865.72,5552.32)
  Inner5 w4: H1.3@3759,6243 3759,6230 3893,6096 4349,6096 4411,6034 5121,6034 5302,5853 5540,5853 5564,5829 5621,5829 5770,5680 5823,5680 5866,5637 5866,5597 5880,5583 5880,5560 5872.32,5552.32 v1(5865.72,5552.32)
PGAOUT0: R26.1 U14.U8 | length 256.1
  Top Layer w6: U14.U8@5766.98,5532.64 5767.34,5533 v1(5787,5533)
  Bottom Layer w3: v1(5787,5533) 5811,5557
  Bottom Layer w6: R26.1@5738,5662.51 5738,5674 5744,5680 5796,5680 5811.98,5664.02 5811.98,5557.98 5811,5557
PGAOUT1: R27.1 U14.U10 | length 155.9
  Bottom Layer w6: v1(5766.98,5493.27) 5766.98,5621 5779.51,5633.53 R27.1@5779.51,5644
PHYRSTB0: R90.2 U12.12 U14.D16 | length 1846.9
  Top Layer w5: U14.D16@6022.89,5375.16 v1(6022.89,5395.16) ; U12.12@6068.4,4287.9 v1(6119.2,4287.9) 6140.39,4287.9 R90.2@6140.49,4288
  内层2 w4: v1(6022.89,5395.16) 6077.16,5395.16 6106,5424 6199,5424 6214,5439 6286,5439 6296,5429 6358,5429 6476,5311 6476,4620 6245,4389 6245,4312 6221,4288 6183,4288 6182.9,4287.9 v1(6119.2,4287.9)
PHYRSTB1: R108.2 U13.12 U14.J1 | length 2805.1
  Top Layer w4: U14.J1@5924.46,5670.44 5930,5675.98 5930,5702 5944,5716 5944,5810.72 6041.28,5908 6649,5908 6814,5743 6814,5531 6831,5514 6837,5514 6873,5478 v1(6873,5477)
  Top Layer w6: U13.12@6783.31,4282.41 6851.61,4282.41 R108.2@6853.49,4280.53
  内层2 w4: v1(6838,4279) 6864,4279 6897,4312 6897,4346 6891,4352 6891,4371 6902,4382 6915,4382 6951,4418 6951,4454 6894,4511 6894,4570 6863,4601 6863,5467 v1(6873,5477)
PMU-SCK: R11.2 U4.52 U5.6 U14.AN6 | length 2850.1
  Top Layer w4: v2(4819,5692) 5332.03,5692 5375,5649.03 5375,5617 5416,5576 5448.03,5576 U14.AN6@5452.02,5572.01
  Top Layer w6: R11.2@3551.77,5348.28 3551.77,5391.23 v1(3551,5392) 3564.98,5405.98 U4.52@3574.26,5405.98 ; v1(3833,5244) 3850,5227 3861,5227 3865,5231 3930,5231 3942,5219 3942,5194.56 U5.6@3932.43,5184.99
  Bottom Layer w4: v1(3833,5244) 3818,5229 3621,5229 3577,5273 3577,5359 3551,5385 v1(3551,5392) 3560,5401 3570.62,5401 3594.62,5377 3785,5377 3839,5431 3839,5589 3915,5665 4760,5665 4787,5692 v2(4819,5692)
PMU-SDA: R12.2 U4.51 U5.5 U14.AN5 | length 2960
  Top Layer w3: U14.AN5@5451.69,5591.36 U14.AN5@5451.95,5591.36
  Top Layer w4: R12.2@3572.77,5348.28 3572.77,5383.77 3594,5405 3594,5418 3591,5421 3574.98,5421 U4.51@3574.25,5421.73 ; v2(4795,5707) 4827,5707 4833,5701 5337,5701 5384,5654 5384,5620 5420,5584 5444.34,5584 5451.69,5591.36 U14.AN5@5452.02,5591.69
  Top Layer w6: v1(3550,5413) 3558.73,5421.73 U4.51@3574.25,5421.73 ; v1(3854,5244) 3856,5242 3934,5242 3956.34,5219.66 U5.5@3956.34,5208.9
  Bottom Layer w4: v1(3854,5244) 3830,5220 3615,5220 3567,5268 3567,5356 3537,5386 3537,5400 v1(3550,5413) 3573,5413 3598,5388 3780,5388 3830,5438 3830,5627 3880,5677 4752,5677 4782,5707 v2(4795,5707)
PS: C12.1 C17.1 C26.1 C29.1 C30.1 C46.1 C55.1 C56.2 C70.2 C79.2 C82.2 C283.2 C284.2 C285.2 C286.2 C287.2 U4.9 U4.15 U4.20 U4.25 U4.31 U4.32 U4.43 U4.44 U4.47 U4.48 U5.2 U5.17 U5.20 | length 1047.9
  Top Layer w8: v1(3694,5592) 3704.86,5602.86 U4.32@3704.86,5615.33 3704.86,5631.14 v1(3702,5634) ; v1(3715,5592) 3720.61,5597.61 U4.31@3720.61,5615.33 ; U4.9@3720.61,5385.61 3720.61,5405.61 v1(3725,5410) ; v1(3779,5508) 3786.53,5500.47 U4.20@3803.97,5500.47 3854.03,5500.47 C17.1@3856.5,5498 ; v1(3779,5586) 3785.79,5579.21 U4.25@3803.97,5579.21 3817.21,5579.21 3844,5606 C12.1@3856.5,5606 ; v1(3782,5429) 3789.27,5421.73 U4.15@3803.97,5421.73 3819.27,5421.73 3827,5414 3827,5400 3839,5388 C55.1@3856.5,5388 ; U5.2@4003.59,5208.9 4003.59,5230.24 v1(4008.84,5235.49) ; v1(4043,5199) 4043.25,5198.75 U5.20@4043.25,5184.99 ; U5.17@4043.25,5137.74 4058.26,5137.74 4064,5132 v1(4064,5106)
  Top Layer w16: C284.2@4034.53,5031.46 4050.46,5031.46 4064,5045 v1(4064,5068.18) v1(4064,5087.54) v1(4064,5106)
  Top Layer w20: C283.2@4034.53,4980.46 C284.2@4034.53,5031.46
  Bottom Layer w4: C46.1@3772.5,5429 v1(3782,5429)
  Bottom Layer w15: v1(3725,5410) 3729,5406 C30.1@3749.5,5406 ; v1(3779,5508) 3784.99,5513.99 C82.2@3784.99,5524 ; v1(3779,5586) 3784.99,5580.01 C56.2@3784.99,5559
  Bottom Layer w20: 3580,5522 v1(3599,5522) ; v1(3599,5460.49) 3589.49,5470 C79.2@3576.01,5470 ; v1(3599,5479) 3585.01,5479 C79.2@3576.01,5470 ; C26.1@3604,5578.01 3604,5546 v1(3599,5541) 3577.29,5541 3576.01,5539.72 C29.1@3576.01,5504.72 C79.2@3576.01,5470 ; C286.2@3678,5646.47 3694,5630.47 v1(3694,5592) ; v1(3715,5592) 3715,5636.47 C285.2@3725,5646.47 ; v1(3779,5508) 3779,5485.47 C287.2@3783,5481.47
  other v1: 4059.07,5238.86
PWRON: C11.1 C97.2 R23.2 U4.6 | length 750.3
  Top Layer w4: C11.1@3681,5349.5 3673.36,5357.14 U4.6@3673.36,5385.61 3673.36,5393.36 v1(3689,5409)
  Top Layer w6: v2(4279,5371) 4279,5391 4289,5401 4306,5401 C97.2@4307,5402 4307.07,5401.93 R23.2@4307.07,5379.2
  内层4 w6: v1(3689,5409) 3705,5393 3775,5393 3781,5387 4263,5387 v2(4279,5371)
RF: C244.2 R72.1 U9.2 | length 145.5
  Top Layer w5: R72.1@3822.08,5986.22 C244.2@3844.57,5986.22 3965.43,5986.22 U9.2@3966.94,5987.73
RGMII0-CLKIN: U12.35 U14.C17 | length 1887.7
  Top Layer w3: U14.C17@6042.49,5355.41 6052.29,5345.61 6095.29,5345.65 6103.65,5354 6114,5354 6117,5357 6126,5357
  Top Layer w4: 6126,5357 6220,5357 v1(6263,5400)
  Top Layer w5: v1(5842,4350.9) U12.35@5871.6,4350.9
  内层2 w4: v1(5842,4350.9) 5848.9,4344 6171,4344 6195,4368 6195,4405 6439,4649 6439,5291 6334,5396 6267,5396 v1(6263,5400)
RGMII0-MDC: U12.13 U14.C16 | length 1713.8
  Top Layer w3: U14.C16@6042.49,5375.11 6052.31,5365.29 6066.18,5365.29 6069.95,5361.52 6090.74,5361.52 6099.09,5369.88 6099.86,5370.65 ; 6099.86,5370.73 6099.86,5371.05
  Top Layer w4: U12.13@6068.4,4303.6 6196.6,4303.6 v1(6199,4306) ; 6099.09,5369.88 6099.86,5370.73 6105.55,5377 6192,5377 v1(6216,5401)
  内层2 w4: v1(6199,4306) 6211,4318 6211,4400 6451,4640 6451,5297 6342,5406 6280,5406 6271,5415 6230,5415 v1(6216,5401)
RGMII0-MDIO: R83.2 U12.14 U14.B16 | length 1735.2
  Top Layer w3: U14.B16@6062.26,5375.16 6073.1,5386 6179,5386 6182,5389
  Top Layer w4: 6182,5389 v1(6194,5401)
  Top Layer w5: U12.14@6068.4,4319.4 6139.89,4319.4 R83.2@6140.49,4320 6140.49,4325.3 6152.19,4337 6193,4337 6211,4319 v1(6229,4319)
  内层2 w4: v1(6194,5401) 6219,5426 6280,5426 6289,5417 6350,5417 6463,5304 6463,4629 6226,4392 6226,4322 v1(6229,4319)
RGMII0-RXCK: R93.2 U12.27 U14.B14 | length 1679.7
  Top Layer w3: U14.B14@6062.19,5414.51 6068.52,5414.51 6078,5405.03 6085.87,5405.03 6097.7,5416.85 6115.15,5416.85 v1(6130,5402)
  Top Layer w5: U12.27@5946.4,4441.4 5946.4,4497.4 5954,4505 v1(5954,4513.49)
  内层2 w4: v1(5954,4513.49) 5963,4504.49 5963,4452 6001,4414 6124,4414 6390,4680 6390,5268 6307,5351 6181,5351 v1(6130,5402)
RGMII0-RXCTL: R95.2 U12.26 U14.D18 | length 1659.7
  Top Layer w5: U12.26@5962.1,4441.4 5962.1,4489.1 5976,4503 v1(5976,4513.49) ; U14.D18@6022.89,5335.78 v1(6022.89,5355.78)
  内层2 w4: v1(5976,4513.49) 5976,4456 6005,4427 6115,4427 6376,4688 6376,5266 6305,5337 6173,5337 6135,5375 6042.11,5375 v1(6022.89,5355.78)
RGMII0-RXD0: R89.1 U12.25 U14.E18 | length 1632.8
  Top Layer w5: U12.25@5977.9,4441.4 5977.9,4481.9 5999,4503 v1(5999,4513.49) ; U14.E18@6003.2,5335.78 v1(6003.2,5355.78)
  内层2 w4: v1(5999,4513.49) 5999,4508 5990,4499 5990,4459 6011,4438 6105,4438 6363,4696 6363,5260 6298,5325 6167,5325 6131,5361 6049,5361 6029,5341 6009.11,5341 6003.2,5346.9 v1(6003.2,5355.78)
RGMII0-RXD1: R86.2 U12.24 U14.F18 | length 1594
  Top Layer w5: U14.F18@5983.52,5335.78 v1(5983.52,5355.78) ; U12.24@5993.6,4441.4 5993.6,4475.6 6023.47,4505.47 v1(6023.47,4513.49)
  内层2 w4: v1(5983.52,5355.78) 5983.52,5350.48 6002.37,5331.63 6038.63,5331.63 6055,5348 6126,5348 6162,5312 6292,5312 6350,5254 6350,4705 6094,4449 6020,4449 6004,4465 6004,4494.02 v1(6023.47,4513.49)
RGMII0-RXD2: R82.2 U12.23 U14.D14 | length 1920.5
  Top Layer w5: U12.23@6009.4,4441.4 6009.4,4469.4 6047,4507 v1(6047,4513.49) ; U14.D14@6022.89,5414.53 v1(6022.89,5434.53)
  内层4 w4: v1(6022.89,5434.53) 6027.47,5434.53 6105,5357 6427,5357 6520,5264 6520,4594 6371,4445 6095,4445 6047,4493 v1(6047,4513.49)
RGMII0-RXD3: R91.1 U12.22 U14.E14 | length 1894.5
  Top Layer w5: U14.E14@6003.2,5414.53 v1(6003.2,5434.53) ; U12.22@6025.1,4441.4 6025.1,4463.1 6072,4510 v1(6072,4513.49)
  内层4 w4: v1(6003.2,5434.53) 6018.72,5419 6027,5419 6100,5346 6420,5346 6509,5257 6509,4598 6367,4456 6101,4456 6062,4495 6062,4503.49 v1(6072,4513.49)
RGMII0-TXCK: U12.20 U14.G12 | length 1984.7
  Top Layer w4: v1(5963,5435) 5963,5453.07 U14.G12@5963.82,5453.9 ; U12.20@6068.4,4413.9 6086.9,4413.9 6097,4424 6194,4424 6223,4395 6289,4395 6311,4417 6358,4417 v1(6373,4402)
  内层2 w3: v1(5963,5435) 5977,5449 6028,5449 6042,5435 6062,5435 6066,5439
  内层2 w4: 6066,5439 6084,5457 6179,5457 6199,5477 6307,5477 6317,5467 6379,5467 6515,5331 6515,4593 6373,4451 v1(6373,4402)
RGMII0-TXCTL: U12.19 U14.F14 | length 1914.8
  Top Layer w4: U12.19@6068.4,4398.1 6089.1,4398.1 6103,4412 6186,4412 6216,4382 6294,4382 6313,4401 v1(6348,4401)
  Top Layer w5: U14.F14@5983.52,5414.53 v1(5983.52,5434.53)
  内层2 w4: v1(5983.52,5434.53) 6000.05,5418 6065,5418 6092,5445 6184,5445 6203,5464 6299,5464 6309,5454 6372,5454 6502,5324 6502,4603 6358,4459 6358,4411 v1(6348,4401)
RGMII0-TXD0: U12.18 U14.E16 | length 1868.3
  Top Layer w4: U12.18@6068.4,4382.4 6094.4,4382.4 6110,4398 6182,4398 6212,4368 6302,4368 6319,4385 v1(6325,4385)
  Top Layer w5: U14.E16@6003.2,5375.16 v1(6003.2,5395.16)
  内层2 w4: v1(6003.2,5395.16) 6017.04,5409 6074,5409 6100,5435 6190,5435 6207,5452 6292,5452 6302,5442 6365,5442 6489,5318 6489,4611 6344,4466 6344,4420 6325,4401 v1(6325,4385)
RGMII0-TXD1: U12.17 U14.B17 | length 1572.5
  Top Layer w3: U14.B17@6062.19,5355.41 6065.19,5352.41 6092.44,5352.41 6107.03,5367 6121,5367
  Top Layer w4: U12.17@6068.4,4366.6 6106.6,4366.6 v1(6110,4370) ; 6121,5367 6206,5367 v1(6240,5401)
  内层2 w4: v1(6110,4370) 6120,4360 6169,4360 6181,4372 6181,4410 6428,4657 6428,5283 6326,5385 6256,5385 v1(6240,5401)
RGMII0-TXD2: U12.16 U14.A14 | length 1475.2
  Top Layer w3: U14.A14@6081.94,5414.53 6092.38,5425 6118.22,5425 6128.22,5415 6138,5415 v1(6151,5402)
  Top Layer w4: U12.16@6068.4,4350.9 6113.9,4350.9 v1(6142,4379)
  内层2 w4: v1(6142,4379) 6151,4388 6151,4420 6403,4672 6403,5272 6312,5363 6190,5363 v1(6151,5402)
RGMII0-TXD3: U12.15 U14.B13 | length 1536.8
  Top Layer w4: U14.B13@6062.26,5434.21 6063.47,5433 6124,5433 6134,5423 6151,5423 v1(6172,5402) ; U12.15@6068.4,4335.1 6124.1,4335.1 6165,4376 v1(6165,4379)
  内层2 w4: v1(6165,4379) 6165,4414 6416,4665 6416,5276 6318,5374 6200,5374 v1(6172,5402)
RGMII1-CLKIN: U13.35 U14.E2 | length 2323.8
  Top Layer w3: U14.E2@6003.09,5650.71 6013.4,5661.02 6013.4,5731.89 6036.9,5755.4 6036.9,5756.02
  Top Layer w4: 6037.03,5756 6096.03,5815 6562,5815 6658,5719 6658,5638 6666,5630 6666,5600 6654,5588 6635,5588 v1(6622,5575)
  Top Layer w6: v1(6558,4345.41) U13.35@6586.51,4345.41
  内层2 w4: v1(6558,4345.41) 6665,4452.41 6665,4486 6650,4501 6650,4531 6677,4558 6677,5331 6645,5363 6645,5489 6622,5512 v1(6622,5575)
RGMII1-MDC: U13.13 U14.H2 | length 2804.7
  Top Layer w3: U14.H2@5944.09,5650.71 5946.67,5653.29 5946.67,5680.46 5956.87,5690.67 5956.87,5743.75 5953.51,5747.11 5953.51,5762.87 5956.06,5765.42
  Top Layer w4: 5956.37,5765.09 5956.37,5802.52 6049.85,5896 6639,5896 6800,5735 6800,5524 6830,5494 6833,5494 v1(6850,5477) ; U13.13@6783.31,4298.11 6882.11,4298.11 6896,4312 6896,4350 v1(6909,4363)
  内层2 w4: v1(6850,5477) 6860,5487 6862,5487 6868,5493 6878,5493 6888,5483 6888,5470 6876,5458 6876,4606 6906,4576 6906,4521 6966,4461 6966,4410 6919,4363 v1(6909,4363)
RGMII1-MDIO: R101.2 U13.14 U14.H3 | length 2678.9
  Top Layer w3: U14.H3@5944.09,5631.01 5953.99,5640.91 5953.99,5677.14 5963.45,5686.6 5963.45,5756.58 5966.62,5759.75 5966.62,5781.91 5967.93,5783.23 ; 5968.16,5783.23 5968.16,5788.65
  Top Layer w4: 5968.16,5788.65 5968.16,5793.26 6058.9,5884 6629,5884 6786,5727 6786,5518 v1(6827,5477) ; R101.2@6853.49,4314 6853.49,4333.49 v1(6865,4345)
  Top Layer w6: U13.14@6783.31,4313.91 6853.4,4313.91 R101.2@6853.49,4314
  内层2 w4: v1(6827,5477) 6848,5456 6848,4598 6878,4568 6878,4506 6935,4449 6935,4424 6906,4395 6893,4395 6880,4382 6880,4360 v1(6865,4345)
RGMII1-RXCK: R111.2 U13.27 U14.J5 | length 2370.5
  Top Layer w4: U14.J5@5924.46,5591.69 v1(5944.46,5591.69)
  Top Layer w6: U13.27@6661.31,4435.91 6661.31,4502.8 v1(6666,4507.49)
  内层2 w4: v1(5944.46,5591.69) 5951.31,5591.69 5974,5569 5996,5569 6008,5581 6008,5776 6046,5814 6583,5814 6668,5729 6668,5662 6645,5639 6630,5639 6615,5624 6615,5604 6638,5581 6638,5518 6659,5497 6659,5369 6689.87,5338.13 6689.87,4547.87 6666,4524 v1(6666,4507.49)
RGMII1-RXCTL: R113.2 U13.26 U14.E1 | length 2146.8
  Top Layer w3: 6003.07,5686.02 6003.07,5733.29 6015.23,5745.46
  Top Layer w4: U14.E1@6003.07,5670.43 6003.07,5686.02 ; 6015.76,5745.46 6015.76,5749.53 6092.23,5826 6573,5826 6673,5726 6673,5646 6680,5639 6680,5596 6656,5572 v1(6656,5526)
  Top Layer w6: U13.26@6677.01,4435.91 6677.01,4487.01 6687,4497 v1(6687,4507.49)
  内层2 w4: v1(6656,5526) 6674,5508 6674,5375 6702,5347 6702,4541 6687,4526 v1(6687,4507.49)
RGMII1-RXD0: R107.1 U13.25 U14.D2 | length 2265.3
  Top Layer w3: U14.D2@6022.79,5650.71 6032.69,5660.61 6032.69,5720.69 6041,5729
  Top Layer w4: 6041,5729 6041,5731.91 6100.09,5791 6365.15,5791 6369.15,5787 6369.15,5777 6373.15,5773 6380.15,5773 6384.15,5777 6384.15,5787 6388.15,5791 6395.15,5791 6399.15,5787 6399.15,5777 6403.15,5773 6410.15,5773 6414.15,5777 6414.15,5787 6418.15,5791 6425.15,5791 6429.15,5787 6429.15,5777 6433.15,5773 6440.15,5773 6444.15,5777 6444.15,5787 6448.15,5791 6455.15,5791 6459.15,5787 6459.15,5777 6463.15,5773 6470.15,5773 6474.15,5777 6474.15,5787 6478.15,5791 6485.15,5791 6489.15,5787 6489.15,5777 6493.15,5773 6500.15,5773 6504.15,5777 6504.15,5787 6508.15,5791 6515.15,5791 6519.15,5787 6519.15,5777 6523.15,5773 6530.15,5773 6534.15,5777 6534.15,5787 6538.15,5791 6546,5791 6631,5706 6631,5681.85 6627,5677.85 6617,5677.85 6613,5673.85 6613,5666.85 6617,5662.85 6627,5662.85 6631,5658.85 6631,5651.85 6627,5647.85 6617,5647.85 6613,5643.85 6613,5636.85 6617,5632.85 6627,5632.85 6631,5628.85 v1(6631,5611)
  Top Layer w6: U13.25@6692.81,4435.91 6692.81,4479.81 6709,4496 v1(6709,4507.49)
  内层2 w4: v1(6631,5611) 6632,5611 6652,5591 6652,5554 6687,5519 6687,5384 6714,5357 6714,4534 6709,4529 v1(6709,4507.49)
RGMII1-RXD1: R104.2 U13.24 U14.D1 | length 2068.8
  Top Layer w3: U14.D1@6022.79,5670.41 6025.69,5673.31 6025.69,5726.99
  Top Layer w4: 6025.69,5726.99 6025.69,5729.27 ; 6025.75,5729.27 6099.48,5803 6553,5803 6644,5712 6644,5621 v1(6652,5613)
  Top Layer w6: U13.24@6708.51,4435.91 6708.51,4475.51 6732,4499 v1(6732,4507.49)
  内层2 w4: v1(6652,5613) 6665,5600 6665,5562 6700,5527 6700,5393 6727,5366 6727,4535 6732,4530 v1(6732,4507.49)
RGMII1-RXD2: R100.2 U13.23 U14.J4 | length 2376.3
  Top Layer w4: U14.J4@5924.46,5611.38 v1(5944.46,5611.38)
  Top Layer w6: U13.23@6724.31,4435.91 6724.31,4475.31 6754,4505 v1(6754,4507.49)
  内层2 w4: v1(5944.46,5611.38) 5977.84,5578 5990,5578 5998,5586 5998,5653 5994,5657 5994,5784 6038,5828 6589,5828 6681,5736 6681,5566 6713,5534 6713,5399 6739,5373 6739,4542 6754,4527 v1(6754,4507.49)
RGMII1-RXD3: R109.1 U13.22 U14.G5 | length 2351.8
  Top Layer w4: U14.G5@5963.83,5591.69 v1(5983.83,5611.69)
  Top Layer w6: U13.22@6740.01,4435.91 6740.01,4469.01 6776,4505 v1(6776,4507.49)
  内层2 w4: v1(5983.83,5611.69) 5969,5626.52 5969,5638 5982,5651 5982,5793 6032,5843 6595,5843 6696,5742 6696,5573 6728,5541 6728,5407 6752,5383 6752,4549 6776,4525 v1(6776,4507.49)
RGMII1-TXCK: U13.20 U14.G1 | length 2376.4
  Top Layer w3: U14.G1@5963.82,5670.43 5963.79,5674.65 5969.95,5680.81 5969.95,5749.27 5976.58,5755.91 5976.58,5761.72
  Top Layer w4: 5976.66,5761.66 5976.66,5782.83 6065.83,5872 6617,5872 6771,5718 6771,5584 v1(6741,5554) ; U13.20@6783.31,4408.41 6796.41,4408.41 6803,4415 v1(6803,4448)
  内层2 w4: v1(6741,5554) 6743,5552 6743,5412 6766,5389 6766,4559 6793,4532 6793,4458 v1(6803,4448)
RGMII1-TXCTL: U13.19 U14.G2 | length 2378.6
  Top Layer w3: U14.G2@5963.79,5650.71 5973.59,5660.51 5973.62,5673.96 5976.95,5677.28 5976.95,5744.9 5986.78,5754.74 5986.78,5763.78
  Top Layer w4: 5986.78,5763.78 5986.78,5774.1 6072.68,5860 6606,5860 6757,5709 6757,5596.66 6752.34,5592 v1(6754,5592) ; U13.19@6783.31,4392.61 6801.61,4392.61 6825,4416 v1(6825,4448)
  内层2 w4: v1(6754,5592) 6754,5567 6758,5563 6758,5420 6779,5399 6779,4565 6806,4538 6806,4467 v1(6825,4448)
RGMII1-TXD0: U13.18 U14.F2 | length 2357.3
  Top Layer w3: U14.F2@5983.39,5650.71 5993.2,5660.52 5993.2,5685.16 5995.16,5687.12 5995.16,5734.97 6006.75,5746.56 6006.75,5757.45
  Top Layer w4: 6006.23,5757 6087.23,5838 6583,5838 6687,5734 6687,5660 6710,5637 v1(6711,5637) ; U13.18@6783.31,4376.91 6806.91,4376.91 6847,4417 v1(6847,4448)
  内层2 w4: v1(6711,5637) 6723,5625 6756,5625 6772,5609 6772,5427 6793,5406 6793,4571 6819,4545 6819,4476 v1(6847,4448)
RGMII1-TXD1: U13.17 U14.F1 | length 2405.4
  Top Layer w3: U14.F1@5983.39,5670.41 5986.2,5673.22 5986.2,5741.02 5996.79,5751.61 5996.79,5765.46 5997.45,5766.09
  Top Layer w4: 5997.45,5766.09 6080.36,5849 6594,5849 6702,5741 6702,5668 6716,5654 6731,5654 v1(6739,5646) ; U13.17@6783.31,4361.11 6812.89,4361.11 6870,4418.23 v1(6870,4448)
  内层2 w4: v1(6739,5646) 6749,5636 6764,5636 6786,5614 6786,5436 6807,5415 6807,4577 6833,4551 6833,4485 v1(6870,4448)
RGMII1-TXD2: U13.16 U14.L5 | length 2613.8
  Top Layer w4: U14.L5@5885.09,5591.69 v1(5905.09,5591.69) ; U13.16@6783.31,4345.41 6817.41,4345.41 6892,4420 v1(6892,4448)
  内层2 w4: v1(5905.09,5591.69) 5920,5606.6 5920,5698 5939,5717 5939,5772 6028,5861 6600,5861 6755,5706 6755,5666 6800,5621 6800,5444 6820,5424 6820,4585 6848,4557 6848,4492 v1(6892,4448)
RGMII1-TXD3: U13.15 U14.L4 | length 2680.1
  Top Layer w4: U14.L4@5885.09,5611.38 v1(5905.09,5611.38) ; U13.15@6783.31,4329.61 6805.39,4329.61 6807,4328 6821,4328 v1(6864,4371)
  内层2 w4: v1(5905.09,5611.38) 5905.09,5701.09 5925,5721 5925,5777 6022,5874 6608,5874 6769,5713 6769,5674 6813,5630 6813,5456 6834,5435 6834,4592 6864,4562 6864,4500 6921,4443 6921,4431 6900,4410 6887,4410 6864,4387 v1(6864,4371)
SAA0: U14.AJ33 UD1.H2 | length 651.1
  Top Layer w3: v3(5508.11,5078.97) 5508.11,5076.78 5520.61,5064.28 5520.61,5050.2 U14.AJ33@5530.43,5040.38
  Top Layer w4.5: UD1.H2@4978.13,5225.67 4990.22,5237.77 5015.08,5237.77 5019.88,5232.97 5053.76,5232.97 5090.76,5195.97 5096.92,5195.97 v3(5110.92,5181.97)
  Inner5 w4.5: v3(5110.92,5181.97) 5130.86,5181.97 5166.86,5145.97 5177.92,5145.97 5208.92,5114.97 5372.92,5114.97 5411.92,5075.97 5505.11,5075.97 v3(5508.11,5078.97)
SAA1: U14.AJ32 UD1.J2 | length 680
  Top Layer w3: v3(5511.92,5099.97) 5521,5090.89 5521,5073.89 5530.43,5064.46 U14.AJ32@5530.43,5060.06
  Top Layer w4.5: UD1.J2@4978.13,5251.26 4992.26,5251.26 5003.97,5262.97 5018.88,5262.97 5024.52,5257.33 5031.28,5257.33 5039.92,5265.97 5053.92,5265.97 5095.92,5223.97 v3(5095.92,5210.97)
  Inner5 w3: 5481,5086.98 5494,5087 5498,5088 v3(5511.92,5099.97)
  Inner5 w4.5: v3(5095.92,5210.97) 5096.37,5210.97 5102.33,5205.01 5128.42,5204.92 5172.87,5160.47 5183.93,5160.47 5213.43,5130.97 5372.42,5130.97 5382.39,5121 5407.16,5121 5441.17,5086.98 5481,5086.98 ; v3@5510.37,5099.97 v3(5511.92,5099.97)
